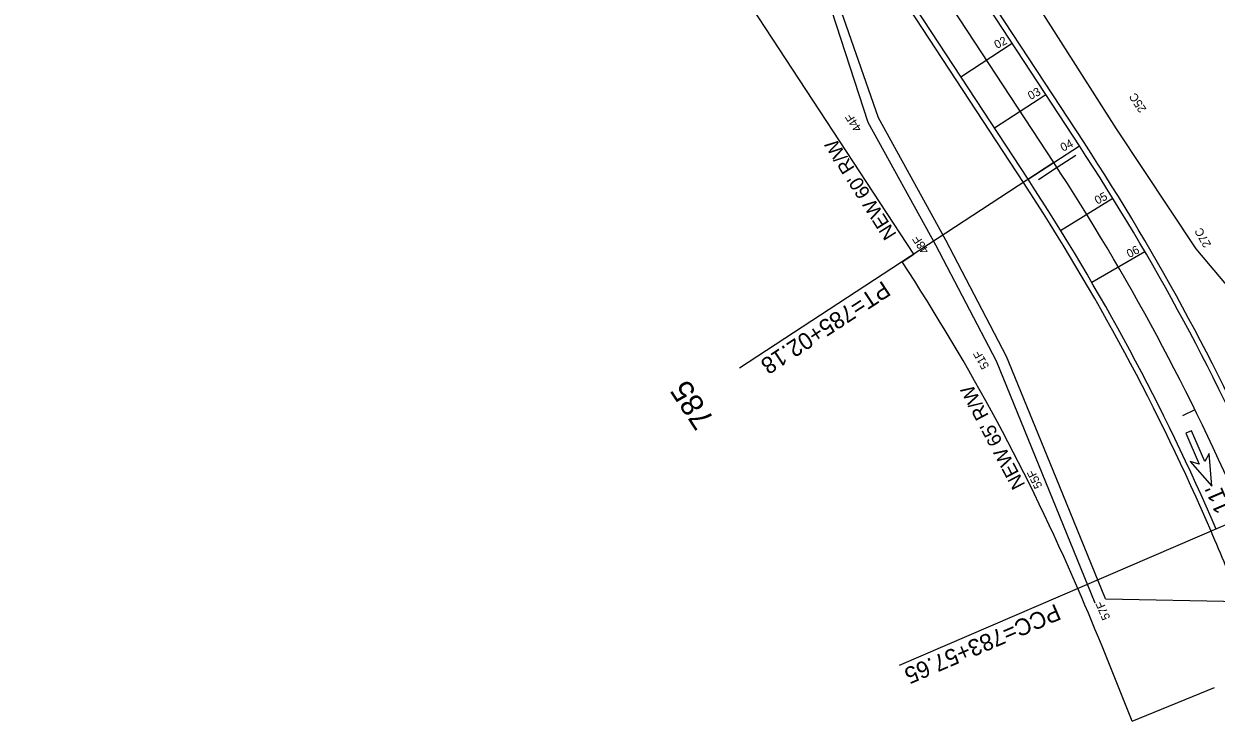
# Model space of a CAD drawing. Extents: x 1551641 to 1624343, y 1119533 to 1136600.
# Drawn here: x 1552463.2 to 1552890.7, y 1133799.3 to 1134049.4 of the extents above; entities that cross this region are included whole.
import ezdxf

# ---------------------------------------------------------------- set-up
doc = ezdxf.new("R2010")
doc.units = 0
for name, color, linetype in [('Prop CMT Pvmt Surface', 7, 'Continuous'), ('RD_HC_Data', 7, 'Continuous'), ('RD_HC_Data_Tic', 7, 'Continuous'), ('RD_HC_TX_Sta50', 7, 'Continuous'), ('RD_Sketch1', 7, 'Continuous'), ('RD_XS_EarthShd', 7, 'Continuous'), ('RD_XS_ExPaveRet', 7, 'Continuous'), ('RD_XS_Pave', 7, 'Continuous'), ('RD_XS_PaveOvlay', 7, 'Continuous'), ('RD_XS_TX_Elev_EX', 7, 'Continuous'), ('RD_XS_TX_Slope', 7, 'Continuous'), ('Scratch_Level_0', 7, 'Continuous')]:
    doc.layers.add(name, color=color, linetype=linetype)

msp = doc.modelspace()

# ---------------------------------------------------------------- linework, layer by layer
at = {"layer": 'Prop CMT Pvmt Surface'}
for p, q in [((1552799.13, 1134030.46), (1552817.53, 1134042.51)), ((1552811.19, 1134012.06), (1552829.59, 1134024.11)), ((1552823.24, 1133993.65), (1552841.65, 1134005.71)), ((1552834.9, 1133975.34), (1552853.61, 1133986.91)), ((1552846.07, 1133956.72), (1552865.08, 1133967.79))]:
    msp.add_line(p, q, dxfattribs=at)
at = {"layer": 'RD_HC_Data'}
for p, q in [((1552832.44, 1133999.68), (1552719.79, 1133925.87)), ((1552900.8, 1133872.54), (1552777.09, 1133819.28))]:
    msp.add_line(p, q, dxfattribs=at)
at = {"layer": 'RD_HC_Data_Tic'}
for p, q in [((1552840.34, 1134002.22), (1552833.64, 1133997.85)), ((1552833.64, 1133997.85), (1552826.94, 1133993.49)), ((1552883.07, 1133911), (1552878.58, 1133908.79))]:
    msp.add_line(p, q, dxfattribs=at)
at = {"layer": 'RD_Sketch1'}
for p, q in [((1552843.32, 1134006.81), (1552718.03, 1134198.02)), ((1552821.57, 1133992.56), (1552697.38, 1134182.1))]:
    msp.add_line(p, q, dxfattribs=at)
for centre, radius, start, end in [((1552135.69, 1133543.15), 846, 23.29239, 33.23375), ((1552135.69, 1133543.15), 820, 23.29239, 33.23375), ((1551585.14, 1133306.13), 1419.4, 22.1864, 23.29239)]:
    msp.add_arc(centre, radius, start, end, dxfattribs=at)
at = {"layer": 'RD_XS_EarthShd'}
for p, q in [((1552841.65, 1134005.71), (1552481.59, 1134555.23)), ((1552823.24, 1133993.65), (1552463.19, 1134543.17))]:
    msp.add_line(p, q, dxfattribs=at)
for radius in [844, 822]:
    msp.add_arc((1552135.69, 1133543.15), radius, 23.29239, 33.23375, dxfattribs=at)
at = {"layer": 'RD_XS_ExPaveRet'}
for p, q in [((1552765.93, 1134014.08), (1552750.16, 1134062.69)), ((1552790.2, 1133969.97), (1552765.93, 1134014.08)), ((1552811.89, 1133928.36), (1552790.2, 1133969.97)), ((1552829.66, 1133885.02), (1552811.89, 1133928.36)), ((1552847.27, 1133841.59), (1552829.66, 1133885.02))]:
    msp.add_line(p, q, dxfattribs=at)
at = {"layer": 'RD_XS_Pave'}
for p, q in [((1552782.26, 1133966.8), (1552660.14, 1134153.17)), ((1552778.08, 1133964.06), (1552782.26, 1133966.8)), ((1552860.53, 1133799.26), (1552890.16, 1133811.34))]:
    msp.add_line(p, q, dxfattribs=at)
for centre, radius, start, end in [((1552135.69, 1133543.15), 768, 23.29239, 33.23375), ((1551585.14, 1133306.13), 1367.4, 21.13881, 23.29239)]:
    msp.add_arc(centre, radius, start, end, dxfattribs=at)
at = {"layer": 'RD_XS_PaveOvlay'}
for p, q in [((1552881.9, 1133903.42), (1552879.83, 1133902.54)), ((1552879.83, 1133902.54), (1552884.55, 1133891.5)), ((1552886.61, 1133892.39), (1552881.9, 1133903.42)), ((1552881.38, 1133892.43), (1552889.18, 1133883.53)), ((1552884.55, 1133891.5), (1552881.38, 1133892.43)), ((1552888.13, 1133895.32), (1552886.61, 1133892.39)), ((1552889.18, 1133883.53), (1552888.13, 1133895.32))]:
    msp.add_line(p, q, dxfattribs=at)
at = {"layer": 'RD_XS_TX_Elev_EX'}
for p, q in [((1552769.61, 1134015.68), (1552752.66, 1134064.35)), ((1552854.91, 1134011.71), (1552828.13, 1134054.02)), ((1552793.73, 1133971.85), (1552769.61, 1134015.68)), ((1552883.55, 1133968.76), (1552854.91, 1134011.71)), ((1552815.52, 1133930.05), (1552793.73, 1133971.85)), ((1552917.57, 1133927.97), (1552883.55, 1133968.76)), ((1552833.37, 1133886.53), (1552815.52, 1133930.05)), ((1552850.98, 1133843.1), (1552833.37, 1133886.53)), ((1552850.98, 1133843.1), (1552899.45, 1133842.13))]:
    msp.add_line(p, q, dxfattribs=at)
at = {"layer": 'Scratch_Level_0'}
msp.add_line((1552832.44, 1133999.68), (1552472.39, 1134549.2), dxfattribs=at)
msp.add_arc((1552135.69, 1133543.15), 833, 23.29239, 33.23375, dxfattribs=at)

# ---------------------------------------------------------------- texts
at = {"layer": 'Prop CMT Pvmt Surface'}
for s, p in [('02', (1552812.09, 1134040.37)), ('03', (1552824.15, 1134022.07)), ('04', (1552835.81, 1134003.49)), ('05', (1552848.08, 1133984.52)), ('06', (1552859.56, 1133965.34))]:
    msp.add_text(s, height=3, rotation=27.7864, dxfattribs=at).set_placement(p)
at = {"layer": 'RD_HC_Data'}
for s, rotation, p in [('PT=785+02.18', 213.2337, (1552771.24, 1133957.46)), ('PCC=783+57.65', 203.2924, (1552833.22, 1133841.52))]:
    msp.add_text(s, height=6, rotation=rotation, dxfattribs=at).set_placement(p)
at = {"layer": 'RD_HC_TX_Sta50'}
msp.add_text('785', height=8, rotation=123.2337, dxfattribs=at).set_placement((1552710.99, 1133907.37))
at = {"layer": 'RD_XS_Pave'}
for s, rotation, p in [("NEW 60' R/W", 122.3587, (1552776.26, 1133973.92)), ("NEW 65' R/W", 117.7788, (1552822.35, 1133884.07))]:
    msp.add_text(s, height=5, rotation=rotation, dxfattribs=at).set_placement(p)
at = {"layer": 'RD_XS_PaveOvlay'}
msp.add_text("11'", height=6, rotation=113.1378, dxfattribs=at).set_placement((1552896.16, 1133875.26))
at = {"layer": 'RD_XS_TX_Slope'}
for s, rotation, p in [('25C', 123.0836, (1552865.8, 1134018.81)), ('44F', 123.2337, (1552763.76, 1134011.84)), ('48F', 123.0836, (1552787.87, 1133968.03)), ('27C', 119.6444, (1552889.02, 1133970.22)), ('51F', 119.6444, (1552809.43, 1133926.58)), ('55F', 116.2053, (1552828.48, 1133883.58)), ('57F', 112.9864, (1552852.8, 1133836.29))]:
    msp.add_text(s, height=3, rotation=rotation, dxfattribs=at).set_placement(p)

doc.saveas('drawing.dxf')
